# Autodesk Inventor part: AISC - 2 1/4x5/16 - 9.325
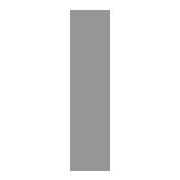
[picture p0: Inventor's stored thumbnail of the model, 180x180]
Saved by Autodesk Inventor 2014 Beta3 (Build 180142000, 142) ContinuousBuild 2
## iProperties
IsCustomPart: 1
Created: 2010-11
Part Number: AISC - 2 1/4x5/16 - 9.325
Material: Steel, Mild
Description: Flat Bar Steel
Document SubType Name: Modeling
Standard: ANSI
Designer: Beta-8540w
Standards Organization: ANSI
Language: en-US
Size Designation: 2 1/4x5/16
Categories: <MemberInstance><Categories><Category DisplayName="Structural Shapes" InternalName="089c4875-fa83-4c05-b084-43b9cc11f5ed" Mnemonic="GRDR"><CategoryParameter Dis
Stock Number: 2 1/4x5/16
Density: 7.86 g/cm^3
Appearance: Steel
_CCFamilyMember: 149
_CCFamilyDisplayName: ANSI AISC (Rectangular) - Flat Bar Steel
_FrameMemberDoc: Frame Member File
_Version: 15.0.0
_GetPNFromCC: 1
G_L: 9.325 in
G_W: 0.313 in
G_H: 2.250 in
Author: Beta-8540w
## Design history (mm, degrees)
node "Start plane"
node "End plane"
node "Driven Length"
  sketch "Sketch3"
    geometry: L1 (0, 0)-(10, 0) reference
    constraints: 2 end point, 1 horizontal
  workplane "Work Plane3"
  sketch "Sketch4"
    geometry: L1 (-2, 0)-(12, 0) reference; L2 (-40.005, 236.864)-(40.005, 236.864) reference
    dimensions: "d9" = 236.86413 distance between parallel lines of L1 L2 (derived)
sketch "Sweep Path"
  geometry: L1 through (25.4, 40.279) direction (-1, 0); L2 through (112.121, 127) direction (-1, 0); 9 other entities
  constraints: 10 horizontal
node "Orientation Work Plane"
feature "Body" dims "d10" = 0
body "Solid1"
sketch "Sketch"
  geometry: L1 (3.969, -28.575)-(-3.969, -28.575); L2 (-3.969, -28.575)-(-3.969, 28.575); L3 (-3.969, 28.575)-(3.969, 28.575); L4 (3.969, 28.575)-(3.969, -28.575); L5 (-6, 0)-(8, 0); L6 (0, -30)-(0, 40); L7 (0, 54)-(0, -44); L8 (-9.2, 0)-(13.2, 0)
  constraints: 16 end point, 2 collinear, 2 parallel, 1 horizontal, 1 perpendicular
  dimensions: "d0" = 57.15 distance between parallel lines of L3 L1 (= G_W); "d1" = 7.9375 distance between parallel lines of L4 L2 (= G_H); "d4" = 3.96875 distance between parallel lines of L6 L4 (= 0.5 x d1); "d5" = 28.575 distance between parallel lines of L5 L3 (= 0.5 x d0)
other parameters: "G_W" = 57.15 [user parameter; used in 1 equation term], "G_H" = 7.9375 [user parameter; used in 1 equation term], "G_L" = 236.86413 (= d9) [user parameter], "G_OFFSET_START" = 0 [user parameter; used in 1 equation term], "G_OFFSET_END" = 0 [user parameter; used in 1 equation term], "d6" = 0 (computed from G_OFFSET_START), "d7" = 236.86413 (= G_OFFSET_END + B_L), "B_L" = 236.86413 [user parameter; used in 1 equation term], "d8" = 90 deg
